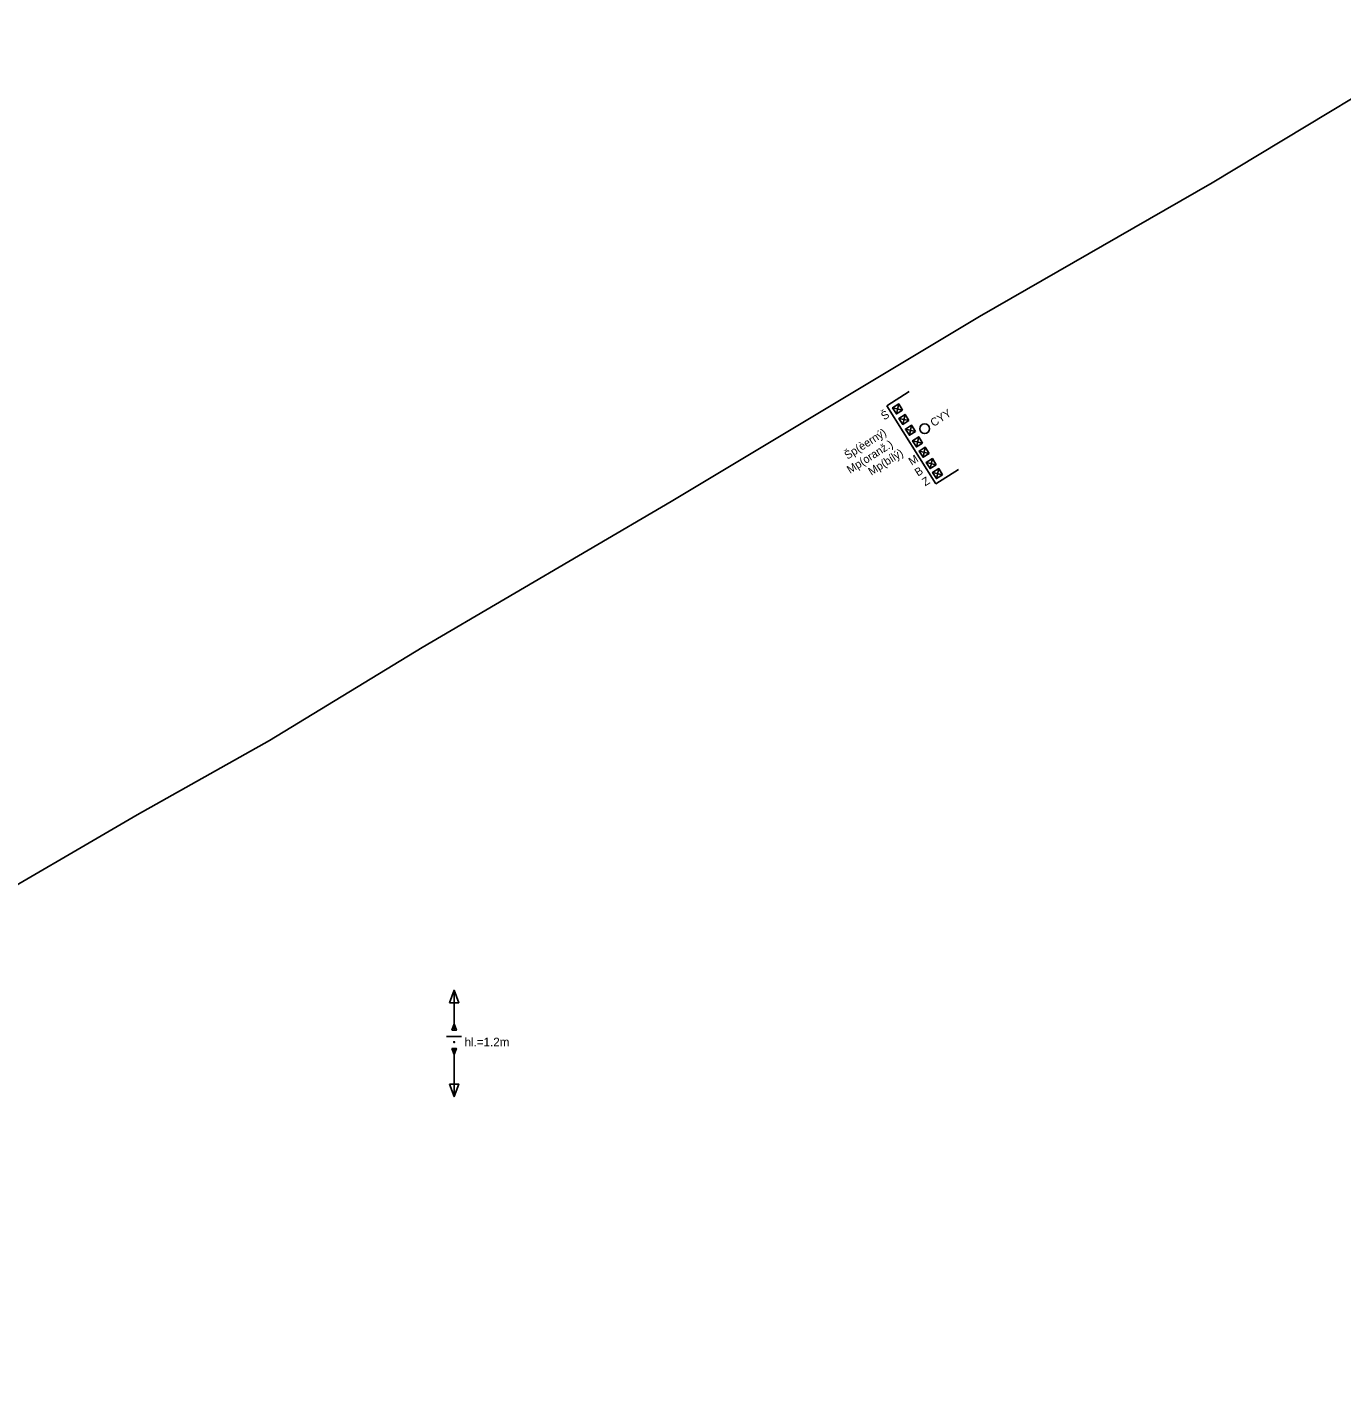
# Model space of a CAD drawing. Extents: x -566419 to -564928, y -1204142 to -1203285.
# Drawn here: x -565519 to -565322, y -1203563.8 to -1203358.1 of the extents above; entities that cross this region are included whole.
import ezdxf

# ---------------------------------------------------------------- set-up
doc = ezdxf.new("R2010")
doc.units = 0
for name, color, linetype in [('Trasa DialT', 7, 'Continuous'), ('Vrstva 10', 7, 'Continuous'), ('Vrstva 58', 7, 'Continuous'), ('Vrstva 61', 7, 'Continuous')]:
    doc.layers.add(name, color=color, linetype=linetype)

msp = doc.modelspace()

# ---------------------------------------------------------------- linework, layer by layer
at = {"layer": 'Trasa DialT'}
msp.add_lwpolyline([(-565653.11, -1203559.27), (-565651.39, -1203561.56), (-565649.55, -1203563.81), (-565641.19, -1203560.67), (-565631.01, -1203554.09), (-565626.71, -1203551.28), (-565615.87, -1203544.51), (-565599.22, -1203536.47), (-565585.44, -1203529.47), (-565560.21, -1203514.82), (-565545.75, -1203503.47), (-565528.16, -1203491.01), (-565502.58, -1203476.14), (-565482.73, -1203465.01), (-565459.85, -1203451.03), (-565422.54, -1203429.16), (-565376.31, -1203401.4), (-565341.42, -1203381.36), (-565302.79, -1203358.08)], dxfattribs=at)
at = {"layer": 'Vrstva 10'}
for p, q in [((-565390.22, -1203414.82), (-565386.84, -1203412.69)), ((-565382.84, -1203426.49), (-565390.22, -1203414.82)), ((-565387.84, -1203415.44), (-565389.34, -1203415.1)), ((-565388.76, -1203416.02), (-565388.42, -1203414.52)), ((-565386.88, -1203417.03), (-565388.38, -1203416.69)), ((-565387.8, -1203417.61), (-565387.46, -1203416.1)), ((-565385.9, -1203418.64), (-565387.4, -1203418.3)), ((-565386.82, -1203419.22), (-565386.48, -1203417.72)), ((-565385.76, -1203420.97), (-565385.42, -1203419.46)), ((-565384.84, -1203420.39), (-565386.34, -1203420.05)), ((-565383.85, -1203421.95), (-565385.35, -1203421.61)), ((-565384.77, -1203422.53), (-565384.43, -1203421.03)), ((-565382.78, -1203423.64), (-565384.28, -1203423.3)), ((-565383.7, -1203424.22), (-565383.36, -1203422.72)), ((-565381.83, -1203425.14), (-565383.33, -1203424.8)), ((-565379.46, -1203424.35), (-565382.84, -1203426.49)), ((-565382.75, -1203425.73), (-565382.41, -1203424.22))]:
    msp.add_line(p, q, dxfattribs=at)
for points in [[(-565387.84, -1203415.44), (-565388.42, -1203414.52), (-565389.34, -1203415.1), (-565388.76, -1203416.02)], [(-565386.88, -1203417.03), (-565387.46, -1203416.1), (-565388.38, -1203416.69), (-565387.8, -1203417.61)], [(-565385.9, -1203418.64), (-565386.48, -1203417.72), (-565387.4, -1203418.3), (-565386.82, -1203419.22)], [(-565384.84, -1203420.39), (-565385.42, -1203419.46), (-565386.34, -1203420.05), (-565385.76, -1203420.97)], [(-565383.85, -1203421.95), (-565384.43, -1203421.03), (-565385.35, -1203421.61), (-565384.77, -1203422.53)], [(-565382.78, -1203423.64), (-565383.36, -1203422.72), (-565384.28, -1203423.3), (-565383.7, -1203424.22)], [(-565381.83, -1203425.14), (-565382.41, -1203424.22), (-565383.33, -1203424.8), (-565382.75, -1203425.73)]]:
    msp.add_lwpolyline(points, close=True, dxfattribs=at)
msp.add_circle((-565384.53, -1203418.25), 0.726, dxfattribs=at)
at = {"layer": 'Vrstva 58'}
for p, q in [((-565455.06, -1203508.44), (-565455.06, -1203502.44)), ((-565456.19, -1203509.38), (-565453.94, -1203509.38)), ((-565455.06, -1203518.38), (-565455.06, -1203511.15))]:
    msp.add_line(p, q, dxfattribs=at)
for points in [[(-565455.75, -1203504.32), (-565455.06, -1203502.44), (-565454.38, -1203504.32)], [(-565455.41, -1203508.44), (-565455.06, -1203507.5), (-565454.72, -1203508.44)], [(-565455.41, -1203511.15), (-565454.72, -1203511.15), (-565455.06, -1203512.09)], [(-565455.75, -1203516.5), (-565455.06, -1203518.38), (-565454.38, -1203516.5)]]:
    msp.add_lwpolyline(points, close=True, dxfattribs=at)
msp.add_circle((-565455.06, -1203510.21), 0.075, dxfattribs=at)

# ---------------------------------------------------------------- texts
at = {"layer": 'Vrstva 10'}
for s, p in [('Š', (-565390.6, -1203417.01)), ('CYY', (-565383.19, -1203418)), ('Šp(èerný)', (-565396.09, -1203422.9)), ('Mp(oranž.)', (-565395.71, -1203425.02)), ('Mp(bílý)', (-565392.51, -1203425.29)), ('M', (-565386.47, -1203423.79)), ('B', (-565385.54, -1203425.44)), ('Z', (-565384.44, -1203426.89))]:
    msp.add_text(s, height=1.2, rotation=32.3288, dxfattribs=at).set_placement(p)
at = {"layer": 'Vrstva 61'}
msp.add_text('hl.=1.2m', height=1.3, dxfattribs=at).set_placement((-565453.5, -1203510.85))

doc.saveas('drawing.dxf')
